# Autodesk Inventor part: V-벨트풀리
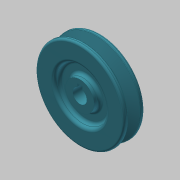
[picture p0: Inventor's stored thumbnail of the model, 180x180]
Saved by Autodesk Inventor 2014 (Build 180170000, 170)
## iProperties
Created: 2019-09
Part Number: V-벨트풀리
Material: 알루미늄 6061
Document SubType Name: Modeling
Designer: mduedu
Density: 1 g/cm^3
Appearance: 커뎃 파란색
Author: mduedu
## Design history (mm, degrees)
sketch "스케치1"
  geometry: L1 (-10, 0)-(10, 0); L2 (10, 0)-(10, 43.5); L3 (10, 43.5)-(-10, 43.5); L4 (-10, 43.5)-(-10, 0); L5 (0, 0)-(0, 43.5); L6 (-5.976, 43.5)-(-2.154, 31); L7 (-2.154, 31)-(2.154, 31); L8 (2.154, 31)-(5.976, 43.5); L9 (-10, 39)-(10, 39); 3 further points
  constraints: 18 end point, 8 point on line, 3 perpendicular, 2 midpoint, 2 parallel, 1 coincident, 1 horizontal, 1 other
  dimensions: "d0" = 87 diameter of L3 L1; "d3" = 12.5 distance between parallel lines of L7 L3; "d4" = 34 deg angle of L8 L6; "d5" = 20 distance between parallel lines of L2 L4; "d6" = 8 distance between parallel lines of L9 L7; "d7" = 9.2 distance of point (4.6, 39) point (-4.6, 39)
revolve "회전1" sketch "스케치1" stored, may be unused: angle "d8" = 90 deg
sketch "스케치2"
  geometry: C1 r 14 at (0, 0); C2 r 25 at (0, 0); 1 further point
  constraints: 2 centre point, 2 coincident
  dimensions: "d9" = 28 diameter of C1; "d10" = 50 diameter of C2
extrude "돌출1" cut sketch "스케치2" distance "d11" = 6; taper "d12" = 0 deg
fillet "모깎기1" dims "d13" = 3
fillet "모깎기2" dims "d14" = 3
fillet "모깎기3" dims "d15" = 0.5, "d16" = 1, "d17" = 2
sketch "스케치3"
  geometry: L1 (-2.5, 6.538)-(2.5, 6.538); L2 (2.5, 6.538)-(2.5, 9.3); L3 (2.5, 9.3)-(-2.5, 9.3); L4 (-2.5, 9.3)-(-2.5, 6.538); A1 r 7 centre (0, 0) between (-2.5, 6.538) and (2.5, 6.538); 1 further point
  constraints: 8 end point, 2 parallel, 2 point on circle, 1 centre point, 1 coincident, 1 horizontal, 1 perpendicular
  dimensions: "d18" = 14 diameter of A1; "d20" = 5 distance of L2.end L3.end; "d21" = 16.3 dimension on A1 L3
extrude "돌출2" cut sketch "스케치3" stored distance "d22" = 6; taper "d23" = 0 deg
node "솔리드1"
mirror "대칭1"
